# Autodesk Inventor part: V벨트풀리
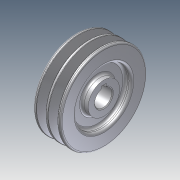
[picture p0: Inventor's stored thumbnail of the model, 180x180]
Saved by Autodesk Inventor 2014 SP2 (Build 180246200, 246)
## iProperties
Company: 한국ATC센터
Created: 2015-02
Part Number: V벨트풀리
Document SubType Name: Modeling
Designer: KYOUNG IL JANG
Density: 1 g/cm^3
Material: 일반
Appearance: 기본값
Author: KYOUNG IL JANG
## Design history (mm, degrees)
sketch "스케치1"
  geometry: L1 (0, 0)-(35, 0); L2 (35, 0)-(35, 55); L3 (35, 55)-(31.062, 55); L4 (31.062, 55)-(27.001, 42.5); L5 (27.001, 42.5)-(22.999, 42.5); L6 (22.999, 42.5)-(18.938, 55); L7 (18.938, 55)-(16.062, 55); L8 (16.062, 55)-(12.001, 42.5); L9 (12.001, 42.5)-(7.999, 42.5); L10 (7.999, 42.5)-(3.938, 55); L11 (3.938, 55)-(0, 55); L12 (0, 55)-(0, 0); L13 (5.4, 50.5)-(14.6, 50.5); L14 (20.4, 50.5)-(29.6, 50.5); 3 further points
  constraints: 28 end point, 8 parallel, 6 collinear, 4 point on line, 3 midpoint, 2 perpendicular, 1 horizontal, 1 vertical alignment
  dimensions: "d0" = 36 deg angle of L8 L10; "d1" = 9.2 distance of L14.start L14.end; "d2" = 4.5 distance between parallel lines of L13 L11; "d3" = 8 distance between parallel lines of L9 L13; "d4" = 10 distance from line of point (25, 42.5) L2; "d5" = 15 distance of point (25, 42.5) point (10, 42.5); "d6" = 35 distance of L1.start L1.end; "d7" = 101 diameter of L14 L1
revolve "회전1" sketch "스케치1" stored, may be unused: angle "d8" = 90 deg
fillet "모깎기1" dims "d9" = 2
fillet "모깎기2" dims "d10" = 0.5
fillet "모깎기3" dims "d11" = 1
sketch "스케치2"
  geometry: L1 (0, 0)-(8, 0); L2 (8, 0)-(8, 20); L3 (8, 20)-(17, 20); L4 (17, 20)-(17, 35); L5 (17, 35)-(0, 35); L6 (0, 35)-(0, 0); L7 (35, 35)-(27, 35); L8 (27, 35)-(27, 20); L9 (27, 20)-(35, 20); L10 (35, 20)-(35, 35); L11 (35, 53)-(35, -53) reference
  constraints: 20 end point, 6 parallel, 3 collinear, 3 perpendicular, 1 horizontal
  dimensions: "d12" = 40 diameter of L9 L1; "d13" = 70 diameter of L7 L1; "d14" = 8 distance between parallel lines of L10 L8; "d15" = 10 distance between parallel lines of L8 L4; "d16" = 9 distance between parallel lines of L4 L2
revolve "회전2" sketch "스케치2" stored, may be unused: angle "d17" = 90 deg
hole "구멍1" diameter "d20" = 22; stored, may be unused: countersink angle "d24" = 90 deg, drill point angle "d26" = 118 deg; dims "d18" = 10, "d19" = 10, "d21" = 6, "d22" = 4, "d23" = 2, "d25" = 8
sketch "스케치3"
  geometry: L1 (-14.8, -3)-(-7.8, -3); L2 (-7.8, -3)-(-7.8, 3); L3 (-7.8, 3)-(-14.8, 3); L4 (-14.8, 3)-(-14.8, -3); C1 r 11 at (0, 0) reference; 2 further points
  constraints: 8 end point, 2 parallel, 1 horizontal, 1 horizontal alignment, 1 midpoint, 1 perpendicular
  dimensions: "d27" = 25.8 dimension on C1 L4; "d28" = 6 distance of L3.end L1.start; "d29" = 7 distance between parallel lines of L4 L2
extrude "돌출1" cut sketch "스케치3" stored distance "d30" = 10; taper "d31" = 0 deg
fillet "모깎기4" dims "d32" = 3
chamfer "모따기1" distance "d33" = 1; stored, may be unused: second distance "d34" = 2, angle "d35" = 45 deg
node "솔리드1"
